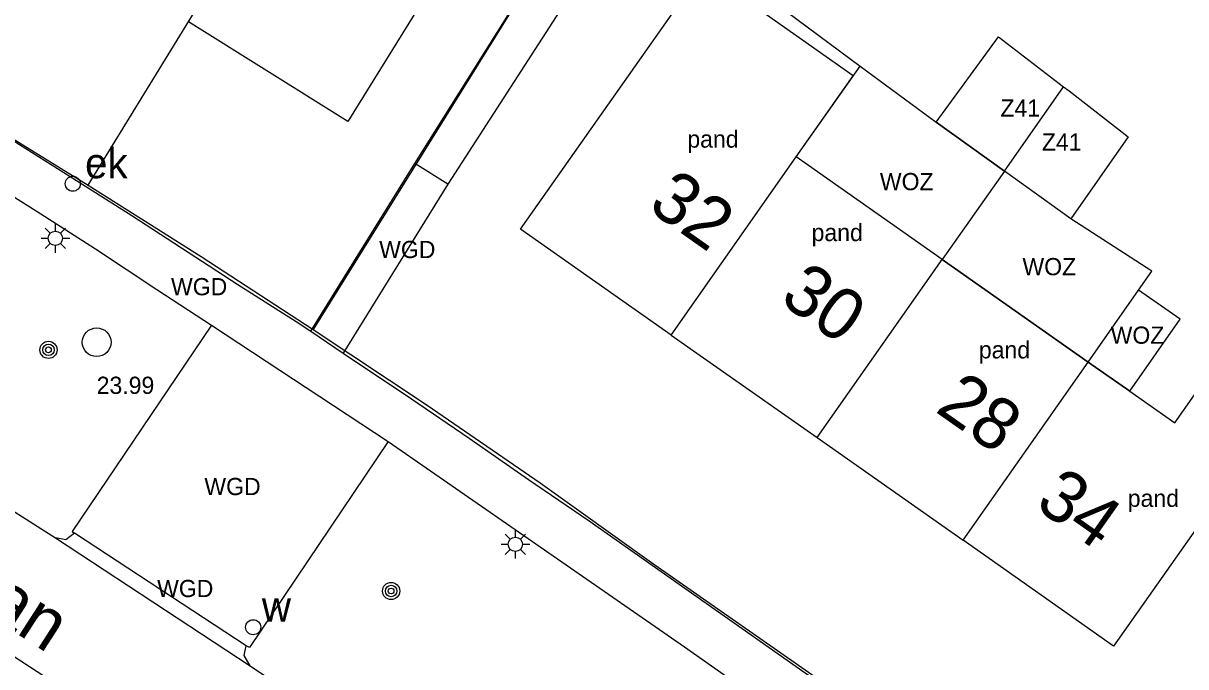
# Model space of a CAD drawing. Extents: x 198240 to 198429, y 356553 to 356721.
# Drawn here: x 198349.04 to 198389.56, y 356658.34 to 356680.75 of the extents above; entities that cross this region are included whole.
import ezdxf

# ---------------------------------------------------------------- set-up
doc = ezdxf.new("R2010")
doc.units = 0
for name, color, linetype in [('(presentatie) Code GPNDDECOM (lijn of vlak) (zonder attributen) niet in de presentatietabel', 7, 'Continuous'), ('bijgebouw', 7, 'Continuous'), ('BOOM', 7, 'Continuous'), ('Elektrakast', 7, 'Continuous'), ('Grens maaiveld', 7, 'Continuous'), ('grens WOZ object', 7, 'Continuous'), ('hoofdgebouw', 7, 'Continuous'), ('Hoogtepunt', 7, 'Continuous'), ('huisnummerreeks BGT', 7, 'Continuous'), ('identificerend kenmerkpunt bijpand', 7, 'Continuous'), ('identificerend kenmerkpunt pand', 7, 'Continuous'), ('identificerend kenmerkpunt WOZ object', 7, 'Continuous'), ('Inspectieput_rioolput', 7, 'Continuous'), ('kant verharding', 7, 'Continuous'), ('LICHTMAST', 7, 'Continuous'), ('muur breder dan 30cm', 7, 'Continuous'), ('openbare ruimte label tekst', 7, 'Continuous'), ('perceelsgrens_definitief', 7, 'Continuous'), ('tussenmuur', 7, 'Continuous'), ('tussenmuur bijgebouw (GBKN Zuid)', 7, 'Continuous'), ('vlakafsluiter', 7, 'Continuous'), ('waterleidingput', 7, 'Continuous'), ('wegdeel kenmerkpunt', 7, 'Continuous'), ('weginrichtingselement lijn', 7, 'Continuous')]:
    doc.layers.add(name, color=color, linetype=linetype)

msp = doc.modelspace()

# ---------------------------------------------------------------- linework, layer by layer
at = {"layer": '(presentatie) Code GPNDDECOM (lijn of vlak) (zonder attributen) niet in de presentatietabel'}
msp.add_lwpolyline([(198375.042, 356681.183), (198375.278, 356681.425), (198378.209, 356679.263)], dxfattribs=at)
at = {"layer": 'bijgebouw'}
for p, q in [((198383.236, 356675.606), (198380.863, 356677.305)), ((198385.555, 356673.945), (198383.236, 356675.606))]:
    msp.add_line(p, q, dxfattribs=at)
at = {"layer": 'BOOM'}
for centre, radius in [((198349.922, 356669.378), 0.3), ((198349.922, 356669.378), 0.2), ((198349.922, 356669.378), 0.1), ((198361.864, 356660.98), 0.3), ((198361.864, 356660.98), 0.2), ((198361.864, 356660.98), 0.1)]:
    msp.add_circle(centre, radius, dxfattribs=at)
at = {"layer": 'Elektrakast'}
msp.add_circle((198350.769, 356675.164), 0.263, dxfattribs=at)
msp.add_circle((198350.769, 356675.164), 0.263, dxfattribs=at)
at = {"layer": 'Grens maaiveld'}
msp.add_line((198355.61, 356670.236), (198361.758, 356666.189), dxfattribs=at)
for points in [[(198371.628, 356669.894), (198366.378, 356673.581), (198372.816, 356682.746), (198375.042, 356681.183)], [(198375.985, 356676.097), (198377.965, 356678.916), (198374.951, 356681.05), (198375.042, 356681.183)], [(198372.981, 356641.75), (198367.706, 356645.661), (198366.187, 356646.802), (198364.538, 356647.958), (198362.833, 356649.176), (198361.195, 356650.33), (198359.548, 356651.463), (198357.799, 356652.691), (198352.878, 356655.977), (198347.848, 356659.26), (198346.187, 356660.353), (198344.459, 356661.463), (198342.759, 356662.483), (198340.988, 356663.592), (198339.269, 356664.603), (198335.834, 356666.664), (198332.346, 356668.725), (198327.175, 356671.678), (198323.573, 356673.677), (198320.05, 356675.592), (198317.553, 356676.932)]]:
    msp.add_lwpolyline(points, dxfattribs=at)
at = {"layer": 'grens WOZ object'}
for p, q in [((198375.985, 356676.097), (198378.209, 356679.263)), ((198378.209, 356679.263), (198380.863, 356677.305)), ((198380.863, 356677.305), (198383.236, 356675.606)), ((198381.072, 356672.526), (198375.985, 356676.097)), ((198383.236, 356675.606), (198381.072, 356672.526)), ((198388.38, 356672.119), (198385.555, 356673.945)), ((198381.072, 356672.526), (198386.16, 356668.955)), ((198387.916, 356671.457), (198388.38, 356672.119)), ((198386.16, 356668.955), (198387.916, 356671.457)), ((198389.362, 356670.442), (198387.916, 356671.457)), ((198387.606, 356667.94), (198389.362, 356670.442)), ((198386.16, 356668.955), (198387.606, 356667.94))]:
    msp.add_line(p, q, dxfattribs=at)
at = {"layer": 'hoofdgebouw'}
for p, q in [((198385.297, 356678.541), (198385.49, 356678.394)), ((198381.072, 356672.526), (198375.985, 356676.097)), ((198386.16, 356668.955), (198381.072, 356672.526)), ((198371.628, 356669.894), (198376.714, 356666.321)), ((198387.606, 356667.94), (198386.16, 356668.955)), ((198376.714, 356666.321), (198381.8, 356662.748))]:
    msp.add_line(p, q, dxfattribs=at)
for points in [[(198358.909, 356687.493), (198362.19, 356685.446), (198364.369, 356688.955), (198366.68, 356687.52), (198360.355, 356677.335), (198354.799, 356680.803)], [(198380.863, 356677.305), (198383.031, 356680.276), (198385.297, 356678.541)], [(198385.49, 356678.394), (198387.552, 356676.799), (198385.555, 356673.945)], [(198387.606, 356667.94), (198389.176, 356666.838), (198391.229, 356669.763), (198393.474, 356668.18), (198387.045, 356659.064), (198381.8, 356662.748)]]:
    msp.add_lwpolyline(points, dxfattribs=at)
at = {"layer": 'Inspectieput_rioolput'}
msp.add_circle((198351.603, 356669.644), 0.5, dxfattribs=at)
at = {"layer": 'kant verharding'}
for p, q in [((198362.69, 356675.866), (198377.035, 356698.715)), ((198359.064, 356670.025), (198360.197, 356669.267)), ((198356.818, 356659.072), (198350.832, 356662.992)), ((198350.163, 356662.829), (198356.948, 356658.373))]:
    msp.add_line(p, q, dxfattribs=at)
for points in [[(198378.362, 356700.859), (198379.92, 356700.023), (198363.843, 356675.152)], [(198325.044, 356691.174), (198339.161, 356682.588), (198341.279, 356681.288), (198343.379, 356680.014), (198351.339, 356675.001), (198352.823, 356674.056), (198356.526, 356671.657), (198358.554, 356670.367), (198359.064, 356670.025)], [(198335.12, 356672.056), (198340.038, 356680.08), (198342.098, 356678.821), (198343.768, 356677.785), (198345.52, 356676.719), (198349.498, 356674.217), (198351.562, 356672.893), (198353.696, 356671.479), (198355.61, 356670.236)], [(198335.12, 356672.056), (198335.329, 356671.939), (198337.026, 356670.919), (198338.761, 356669.905), (198342.174, 356667.852), (198343.856, 356666.8), (198345.587, 356665.739), (198350.163, 356662.829)], [(198355.61, 356670.236), (198350.746, 356663.05), (198350.832, 356662.992)], [(198360.197, 356669.267), (198362.576, 356667.673), (198364.582, 356666.298), (198366.655, 356664.862), (198368.765, 356663.429), (198386.018, 356651.295)], [(198361.758, 356666.189), (198356.926, 356659.012), (198356.818, 356659.072)], [(198361.758, 356666.189), (198372.084, 356659.041), (198383.655, 356650.892), (198378.215, 356643.352)], [(198350.832, 356662.992), (198350.527, 356662.765), (198350.163, 356662.829)], [(198356.948, 356658.373), (198356.745, 356658.732), (198356.818, 356659.072)], [(198356.948, 356658.373), (198360.581, 356655.932), (198363.871, 356653.655), (198365.49, 356652.496), (198367.13, 356651.344), (198368.743, 356650.174), (198375.533, 356645.157)]]:
    msp.add_lwpolyline(points, dxfattribs=at)
at = {"layer": 'LICHTMAST'}
for p, q in [((198349.986, 356673.44), (198349.809, 356673.617)), ((198350.163, 356673.513), (198350.163, 356673.763)), ((198350.34, 356673.44), (198350.517, 356673.617)), ((198349.663, 356673.263), (198349.913, 356673.263)), ((198350.413, 356673.263), (198350.663, 356673.263)), ((198349.809, 356672.909), (198349.986, 356673.086)), ((198350.163, 356672.763), (198350.163, 356673.013)), ((198350.517, 356672.909), (198350.34, 356673.086)), ((198366.194, 356662.857), (198366.194, 356663.107)), ((198365.694, 356662.607), (198365.944, 356662.607)), ((198366.017, 356662.784), (198365.84, 356662.961)), ((198366.371, 356662.784), (198366.548, 356662.961)), ((198366.444, 356662.607), (198366.694, 356662.607)), ((198365.84, 356662.253), (198366.017, 356662.43)), ((198366.194, 356662.107), (198366.194, 356662.357)), ((198366.548, 356662.253), (198366.371, 356662.43))]:
    msp.add_line(p, q, dxfattribs=at)
for centre in [(198350.163, 356673.263), (198366.194, 356662.607)]:
    msp.add_circle(centre, 0.25, dxfattribs=at)
at = {"layer": 'muur breder dan 30cm'}
for p, q in [((198359.064, 356670.025), (198362.69, 356675.866)), ((198363.843, 356675.152), (198360.197, 356669.267))]:
    msp.add_line(p, q, dxfattribs=at)
at = {"layer": 'perceelsgrens_definitief'}
for points in [[(198351.308, 356675.119), (198358.955, 356687.569), (198361.716, 356691.988), (198371.934, 356708.659)], [(198371.934, 356708.659), (198378.011, 356706.528), (198378.641, 356708.364), (198382.147, 356707.061), (198359.148, 356670.092)], [(198347.687, 356677.346), (198351.308, 356675.119)], [(198351.308, 356675.119), (198355.245, 356672.631), (198359.148, 356670.092)], [(198359.148, 356670.092), (198363.123, 356667.45), (198367.055, 356664.745), (198370.943, 356661.977)], [(198370.943, 356661.977), (198385.92, 356651.508)]]:
    msp.add_lwpolyline(points, dxfattribs=at)
at = {"layer": 'tussenmuur'}
for p, q in [((198371.628, 356669.894), (198375.985, 356676.097)), ((198376.714, 356666.321), (198381.072, 356672.526)), ((198381.8, 356662.748), (198386.16, 356668.955))]:
    msp.add_line(p, q, dxfattribs=at)
at = {"layer": 'tussenmuur bijgebouw (GBKN Zuid)'}
msp.add_line((198383.236, 356675.606), (198385.297, 356678.541), dxfattribs=at)
at = {"layer": 'vlakafsluiter'}
msp.add_line((198363.843, 356675.152), (198362.69, 356675.866), dxfattribs=at)
at = {"layer": 'waterleidingput'}
msp.add_circle((198357.056, 356659.717), 0.263, dxfattribs=at)
msp.add_circle((198357.056, 356659.717), 0.263, dxfattribs=at)
at = {"layer": 'weginrichtingselement lijn'}
msp.add_lwpolyline([(198372.981, 356641.75), (198367.706, 356645.661), (198366.187, 356646.802), (198364.538, 356647.958), (198362.833, 356649.176), (198361.195, 356650.33), (198359.548, 356651.463), (198357.799, 356652.691), (198352.878, 356655.977), (198347.848, 356659.26), (198346.187, 356660.353), (198344.459, 356661.463), (198342.759, 356662.483), (198340.988, 356663.592), (198339.269, 356664.603), (198335.834, 356666.664), (198332.346, 356668.725), (198327.175, 356671.678), (198323.573, 356673.677), (198320.05, 356675.592), (198317.553, 356676.932)], dxfattribs=at)

# ---------------------------------------------------------------- texts
at = {"layer": 'Elektrakast'}
msp.add_text('ek', height=1.05, dxfattribs=at).set_placement((198351.198, 356675.355))
at = {"layer": 'Hoogtepunt'}
msp.add_text('23.99', height=0.6, dxfattribs=at).set_placement((198351.603, 356667.844))
msp.add_text('23.99', height=0.6, dxfattribs=at).set_placement((198351.603, 356667.844))
at = {"layer": 'huisnummerreeks BGT'}
for s, rotation, p in [('32', 324.9, (198370.764, 356674.29)), ('30', 324.9, (198375.357, 356671.063)), ('28', 324.9, (198380.786, 356667.25)), ('34', 324.8, (198384.256, 356663.911))]:
    msp.add_text(s, height=1.8, rotation=rotation, dxfattribs=at).set_placement(p)
at = {"layer": 'identificerend kenmerkpunt bijpand'}
for p in [(198383.098, 356677.499), (198384.543, 356676.316)]:
    msp.add_text('Z41', height=0.6, dxfattribs=at).set_placement(p)
at = {"layer": 'identificerend kenmerkpunt pand'}
for p in [(198372.188, 356676.42), (198376.519, 356673.165), (198382.348, 356669.08), (198387.538, 356663.91)]:
    msp.add_text('pand', height=0.6, dxfattribs=at).set_placement(p)
at = {"layer": 'identificerend kenmerkpunt WOZ object'}
for p in [(198378.897, 356674.939), (198383.867, 356671.977), (198386.941, 356669.59)]:
    msp.add_text('WOZ', height=0.6, dxfattribs=at).set_placement(p)
at = {"layer": 'openbare ruimte label tekst'}
msp.add_text('Beatrixlaan', height=1.8, rotation=327.1, dxfattribs=at).set_placement((198339.771, 356665.343))
at = {"layer": 'waterleidingput'}
msp.add_text('w', height=1.05, dxfattribs=at).set_placement((198357.36, 356659.915))
at = {"layer": 'wegdeel kenmerkpunt'}
for p in [(198361.448, 356672.575), (198354.193, 356671.279), (198355.356, 356664.319), (198353.709, 356660.767)]:
    msp.add_text('WGD', height=0.6, dxfattribs=at).set_placement(p)

doc.saveas('drawing.dxf')
